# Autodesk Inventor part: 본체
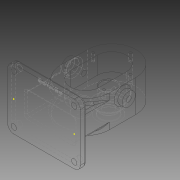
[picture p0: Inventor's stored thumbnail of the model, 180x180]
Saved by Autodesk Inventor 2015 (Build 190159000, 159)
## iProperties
Created: 2020-09
Part Number: 본체
Material: 일반
Document SubType Name: Modeling
Designer: Administrator
Density: 1 g/cm^3
Appearance: 기본값
Author: Administrator
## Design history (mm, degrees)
sketch "스케치1"
  geometry: L1 (-60, 50)-(60, 50); L2 (60, 50)-(60, -50); L3 (60, -50)-(-60, -50); L4 (-60, -50)-(-60, 50); L5 (-60, 50)-(60, -50); L6 (60, 50)-(-60, -50); 1 further point
  constraints: 12 end point, 2 midpoint, 2 parallel, 1 horizontal, 1 perpendicular
  dimensions: "d0" = 120 distance of L2.end L3.end; "d1" = 100 distance of L1.end L2.end
extrude "돌출1" new body sketch "스케치1" distance "d2" = 10; taper "d3" = 0 deg
fillet "모깎기1" dims "d4" = 10
node "작업 평면1"
sketch "스케치3"
  geometry: L1 (0, -25)-(0, 12); L2 (106.75, -50)-(120.75, -50); L3 (152, -33)-(152, 20); L4 (152, 20)-(90, 20); L5 (0, 12)-(28, 12); L6 (28, 12)-(28, -25); L7 (28, -25)-(0, -25); L8 (90, 20)-(136, 20); L9 (136, 20)-(136, -9); L10 (136, -9)-(119.25, -9); L11 (119.25, -9)-(119.25, -24); L12 (119.25, -9)-(106.75, -9); L13 (106.75, -9)-(106.75, -24); L14 (90, 20)-(90, -9); L15 (90, -9)-(106.75, -9); L16 (119.25, -24)-(115.25, -24); L17 (115.25, -24)-(115.25, -42); L18 (115.25, -42)-(120.75, -42); L19 (120.75, -42)-(120.75, -50); L20 (106.75, -24)-(106.75, -50); L21 (115.25, -24)-(106.75, -24); L22 (115.25, -42)-(106.75, -42); L23 (106.75, -50)-(125.75, -50); L24 (125.75, -50)-(125.75, -33); L25 (125.75, -33)-(152, -33); L26 (106.75, -50)-(87.75, -50); L27 (87.75, -50)-(87.75, -33); L28 (87.75, -33)-(28, -33); L29 (28, -33)-(28, -25); L30 (90, 20)-(28, 20); L31 (28, 20)-(28, 12); L32 (125.75, -33)-(106.75, -33); L33 (90, -9)-(73.25, -9); L34 (73.25, -9)-(73.25, -24); L35 (73.25, -9)-(60.75, -9); L36 (60.75, -9)-(60.75, -24); L37 (60.75, -24)-(73.25, -24); 2 further points
  constraints: 74 end point, 17 perpendicular, 12 horizontal, 5 point on line, 3 vertical, 2 parallel
  dimensions: "d13" = 37 distance of L1.start L1.end; "d16" = 53 distance of L3.start L3.end; "d17" = 62 distance of L3.end L4.end; "d19" = 46 distance of L4.end L8.end; "d20" = 29 distance of L8.end L9.end; "d21" = 16.75 distance of L9.end L10.end; "d22" = 15 distance of L10.end L11.end; "d23" = 12.5 distance of L10.end L12.end; "d24" = 4 distance of L11.end L16.end; "d26" = 5.5 distance of L17.end L18.end; "d27" = 19 distance of L2.start L23.end; "d28" = 17 distance of L23.end L24.end; "d29" = 19 distance of L2.start L26.end; "d30" = 17 distance of L26.end L27.end; "d31" = 62 distance of L4.end L30.end; "d52" = 16.75 distance of L14.end L33.end; "d53" = 15 distance of L33.end L34.end; "d54" = 12.5 distance of L33.end L35.end; "d57" = 152 distance between parallel lines of L1 L3; "d58" = 9 distance between parallel lines of L18 L25; "d59" = 45 distance between parallel lines of L5 L25; "d60" = 152 distance from line of point (0, 0) L3; "d61" = 33 distance from line of point (0, 0) L25
node "작업 평면2"
sketch "스케치4"
  geometry: L1 (0, 0)-(0, 90); L2 (0, 90)-(0, 112); L3 (0, 90)-(0, 68); L4 (-40, 112)-(-40, 68); L5 (40, 112)-(40, 68); A1 r 40 centre (0, 112) between (40, 112) and (-40, 112); A2 r 40 centre (0, 68) between (-40, 68) and (40, 68)
  constraints: 10 end point, 4 point on circle, 3 vertical, 2 centre point, 2 coincident, 2 tangent, 1 parallel, 1 point on line
  dimensions: "d33" = 90 distance of L1.start L1.end; "d34" = 22 distance of L2.end L1.end; "d35" = 40 radius of A1; "d36" = 22 distance of L1.end L3.end; "d37" = 40 radius of A2
extrude "돌출3" join sketch "스케치4" distance "d38" = 53; taper "d39" = 0 deg
sketch "스케치5"
  geometry: L1 (-24, 112)-(-24, 68); L2 (24, 68)-(24, 112); A1 r 40 centre (0, 68) between (-40, 68) and (40, 68) reference; A2 r 24 centre (0, 68) between (-24, 68) and (24, 68); A3 r 40 centre (0, 112) between (40, 112) and (-40, 112) reference; A4 r 24 centre (0, 112) between (24, 112) and (-24, 112); 1 further point
  constraints: 4 end point, 4 point on circle, 2 centre point, 2 coincident, 2 tangent, 1 parallel, 1 vertical
  dimensions: "d40" = 24 radius of A2; "d42" = 24 radius of A4
extrude "돌출4" cut sketch "스케치5" distance "d43" = 29; taper "d44" = 0 deg
node "작업 평면3"
sketch "스케치6"
  geometry: L1 (0, 152)-(0, 125.75); L2 (0, 125.75)-(0, 106.75); C1 r 19 at (0, 106.75); A1 r 40 centre (0, 112) between (40, 112) and (-40, 112) reference; 1 further point
  constraints: 4 end point, 2 vertical, 1 centre point, 1 coincident, 1 point on circle
  dimensions: "d46" = 26.25 distance of L1.start L1.end; "d47" = 19 distance of L1.end L2.end; "d48" = 19 radius of C1
extrude "돌출5" join sketch "스케치6" distance "d49" = 17; taper "d50" = 0 deg
revolve "회전1" stored, may be unused: angle "d51" = 90 deg
node "작업 평면4"
sketch "스케치7"
  geometry: L1 (60.75, -9)-(60.75, -24) reference; L2 (60.75, -24)-(73.25, -24) reference; L3 (60.75, -9)-(60.75, -24); L4 (73.25, -24)-(60.75, -24); L5 (73.25, -24)-(73.25, -9); L6 (73.25, -9)-(60.75, -9); 1 further point
  constraints: 8 end point, 2 perpendicular, 1 collinear, 1 vertical
revolve "회전2" stored, may be unused: angle "d56" = 90 deg
sketch "스케치8"
  geometry: L1 (40, -20)-(40, 33) reference; L2 (-40, -20)-(-40, 33) reference; L3 (24, 9)-(-24, 9) reference; L4 (40, -12)-(40, 25); L5 (40, 25)-(-40, 25); L6 (-40, 25)-(-40, -12); L7 (-40, -12)-(40, -12); 1 further point
  constraints: 8 end point, 4 point on line, 1 parallel, 1 perpendicular
  dimensions: "d65" = 16 distance between parallel lines of L5 L3; "d66" = 21 distance between parallel lines of L7 L3
extrude "돌출6" join sketch "스케치8" distance "d67" = 75.75; taper "d68" = 0 deg
revolve "회전3" stored, may be unused: angle "d69" = 90 deg
sketch "스케치9"
  geometry: L1 (-24, 17.75)-(24, 17.75); L2 (-24, 17.75)-(24, 17.75) reference; L3 (24, 17.75)-(24, 0); L4 (24, 44)-(24, 0) reference; L5 (-24, 0)-(-24, 17.75); A1 r 24 centre (0, 0) between (-24, 0) and (24, 0); 1 further point
  constraints: 6 end point, 2 collinear, 2 point on circle, 2 tangent, 1 centre point, 1 parallel
extrude "돌출7" cut sketch "스케치9" distance "d70" = 21; taper "d71" = 0 deg
sketch "스케치10"
  geometry: L1 (0, 152)-(0, 143); L2 (0, 28)-(0, 37); L3 (-40, 68)-(-40, 112) reference; L4 (-31, 90)-(-31, 112); L5 (-31, 90)-(-31, 68); L6 (40, 68)-(40, 112) reference; L7 (31, 90)-(31, 112); L8 (31, 90)-(31, 68); A1 r 40 centre (0, 112) between (40, 112) and (-40, 112) reference; A2 r 40 centre (0, 68) between (-40, 68) and (40, 68) reference; 1 further point
  constraints: 12 end point, 4 vertical, 2 point on circle
  dimensions: "d72" = 9 distance of L1.start L1.end; "d73" = 9 distance of L2.start L2.end; "d75" = 22 distance of L4.start L4.end; "d76" = 22 distance of L4.start L5.end; "d78" = 22 distance of L7.start L7.end; "d79" = 22 distance of L7.start L8.end; "d80" = 9 distance between parallel lines of L6 L8; "d81" = 40 distance between parallel lines of L6 L1; "d82" = 40 distance between parallel lines of L6 L2; "d83" = 71 distance between parallel lines of L6 L5; "d84" = 9 distance from line of L6.end L7; "d85" = 71 distance from line of L6.end L4; "d86" = 9 distance of L6.end L7.end; "d87" = 71 distance of L6.end L4.end
hole "구멍1" sketch "스케치10" at (0, 143), (-31, 112), (-31, 68), (0, 37), (31, 68), (31, 112) diameter "d88" = 4.134; stored, may be unused: countersink angle "d92" = 90 deg, drill point angle "d94" = 118 deg; dims "d89" = 10, "d90" = 4, "d91" = 2, "d93" = 12
sketch "스케치11"
  geometry: L1 (-60, 40)-(-60, -40) reference; L2 (40, -12)-(-40, -12) reference; L3 (-40, -12)-(-40, 25) reference; L4 (-40, 25)-(40, 25) reference; L5 (40, 25)-(40, -12) reference; L6 (50, 50)-(-50, 50) reference; L7 (-60, 40)-(-60, -40) reference; L8 (-50, -50)-(50, -50) reference; L9 (60, -40)-(60, 40) reference; C1 r 4.5 at (-50, -40); C2 r 4.5 at (-50, 40); C3 r 4.5 at (50, 40); C4 r 4.5 at (50, -40); A1 r 10 centre (-50, -40) between (-60, -40) and (-50, -50) reference; A2 r 10 centre (50, 40) between (60, 40) and (50, 50) reference; A3 r 10 centre (-50, 40) between (-50, 50) and (-60, 40) reference; A4 r 10 centre (-50, -40) between (-60, -40) and (-50, -50) reference; A5 r 10 centre (50, -40) between (50, -50) and (60, -40) reference; 1 further point
  constraints: 4 centre point, 1 coincident
  dimensions: "d99" = 4.5 radius of C1; "d100" = 4.5 radius of C2; "d101" = 4.5 radius of C3; "d102" = 4.5 radius of C4
extrude "돌출8" cut sketch "스케치11" distance "d103" = 21; taper "d104" = 0 deg
fillet "모깎기2" dims "d105" = 3
chamfer "모따기1" distance "d106" = 1; stored, may be unused: second distance "d107" = 2, angle "d108" = 45 deg
node "작업 평면5"
sketch "스케치12"
  geometry: L1 (40, 112)-(40, 68) reference; L2 (40, 90)-(50, 90); L3 (50, 90)-(50, 101); L4 (50, 101)-(40, 101); L5 (-40, 112)-(-40, 68) reference; L6 (-40, 90)-(-50, 90); L7 (-50, 90)-(-50, 101); L8 (-50, 101)-(-40, 101); 1 further point
  constraints: 12 end point, 4 perpendicular, 2 horizontal, 2 midpoint, 2 point on line
  dimensions: "d110" = 10 distance of L2.start L2.end; "d111" = 11 distance of L2.end L3.end; "d112" = 10 distance of L6.start L6.end; "d113" = 11 distance of L6.end L7.end
revolve "회전4" sketch "스케치12" stored, may be unused: angle "d114" = 90 deg
fillet "모깎기3" dims "d115" = 3
sketch "스케치13"
  geometry: 1 further point
hole "구멍2" diameter "d118" = 8.376; stored, may be unused: countersink angle "d122" = 90 deg, drill point angle "d124" = 118 deg; dims "d119" = 30, "d120" = 4, "d121" = 2, "d123" = 37.3, "d136" = 10, "d137" = 10
sketch "스케치14"
  geometry: 1 further point
hole "구멍3" diameter "d127" = 8.376; stored, may be unused: countersink angle "d131" = 90 deg, drill point angle "d133" = 118 deg; dims "d128" = 30, "d129" = 4, "d130" = 2, "d132" = 37.3, "d138" = 10, "d139" = 10
chamfer "모따기2" distance "d134" = 0.7; stored, may be unused: second distance "d135" = 2, angle "d140" = 45 deg
sketch "스케치15"
  geometry: L1 (-60, 40)-(-60, -40) reference; L2 (-50, -50)-(50, -50) reference; A1 r 10 centre (-50, -40) between (-60, -40) and (-50, -50) reference; 2 further points
  constraints: 1 other
  dimensions: "d141" = 60 distance from line of L1 point (0, -38); "d142" = 12 distance from line of L2 point (0, -38)
feature "엠보싱1" sketch "스케치15" dims "d143" = 0.5, "d144" = 0
fillet "모깎기4" dims "d145" = 0.5
node "솔리드1"
node "투영된 루프2"
other parameters: "d11" = 0, "d45" = -33, "d55" = 0, "d109" = 5
